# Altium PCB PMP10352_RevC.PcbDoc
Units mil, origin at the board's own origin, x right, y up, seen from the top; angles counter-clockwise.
Board outline 1810 x 910 mil, 4 copper layers (Top Layer, MidLayer1, MidLayer2, Bottom Layer), stack 61.2 mil thick; 57 components, 29 nets, 148 pads, 42 vias.
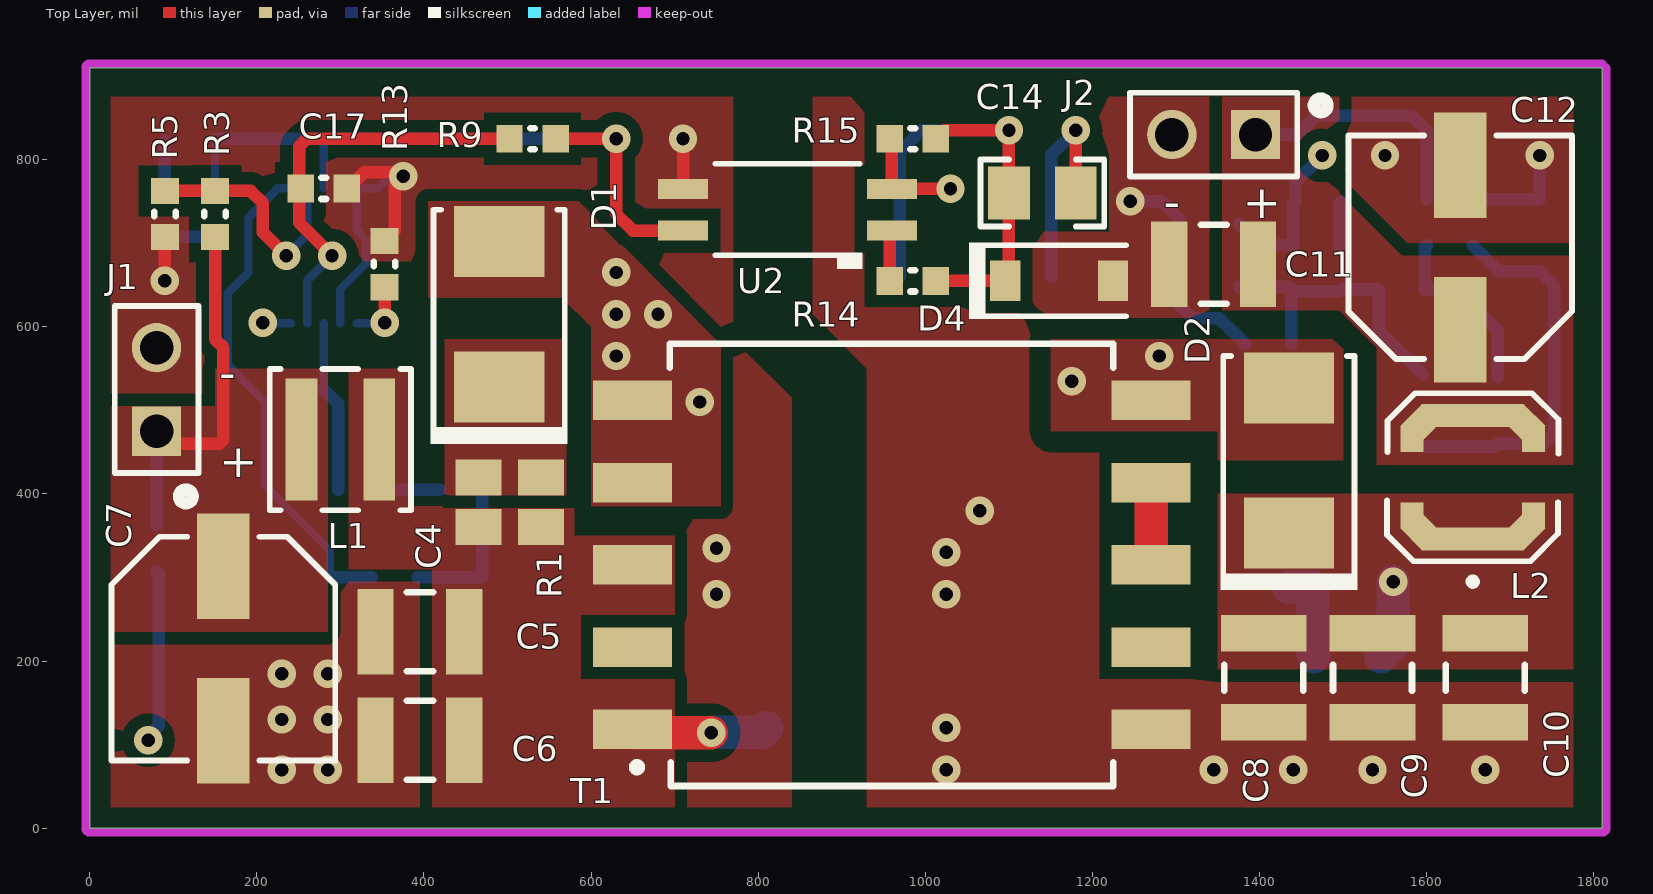
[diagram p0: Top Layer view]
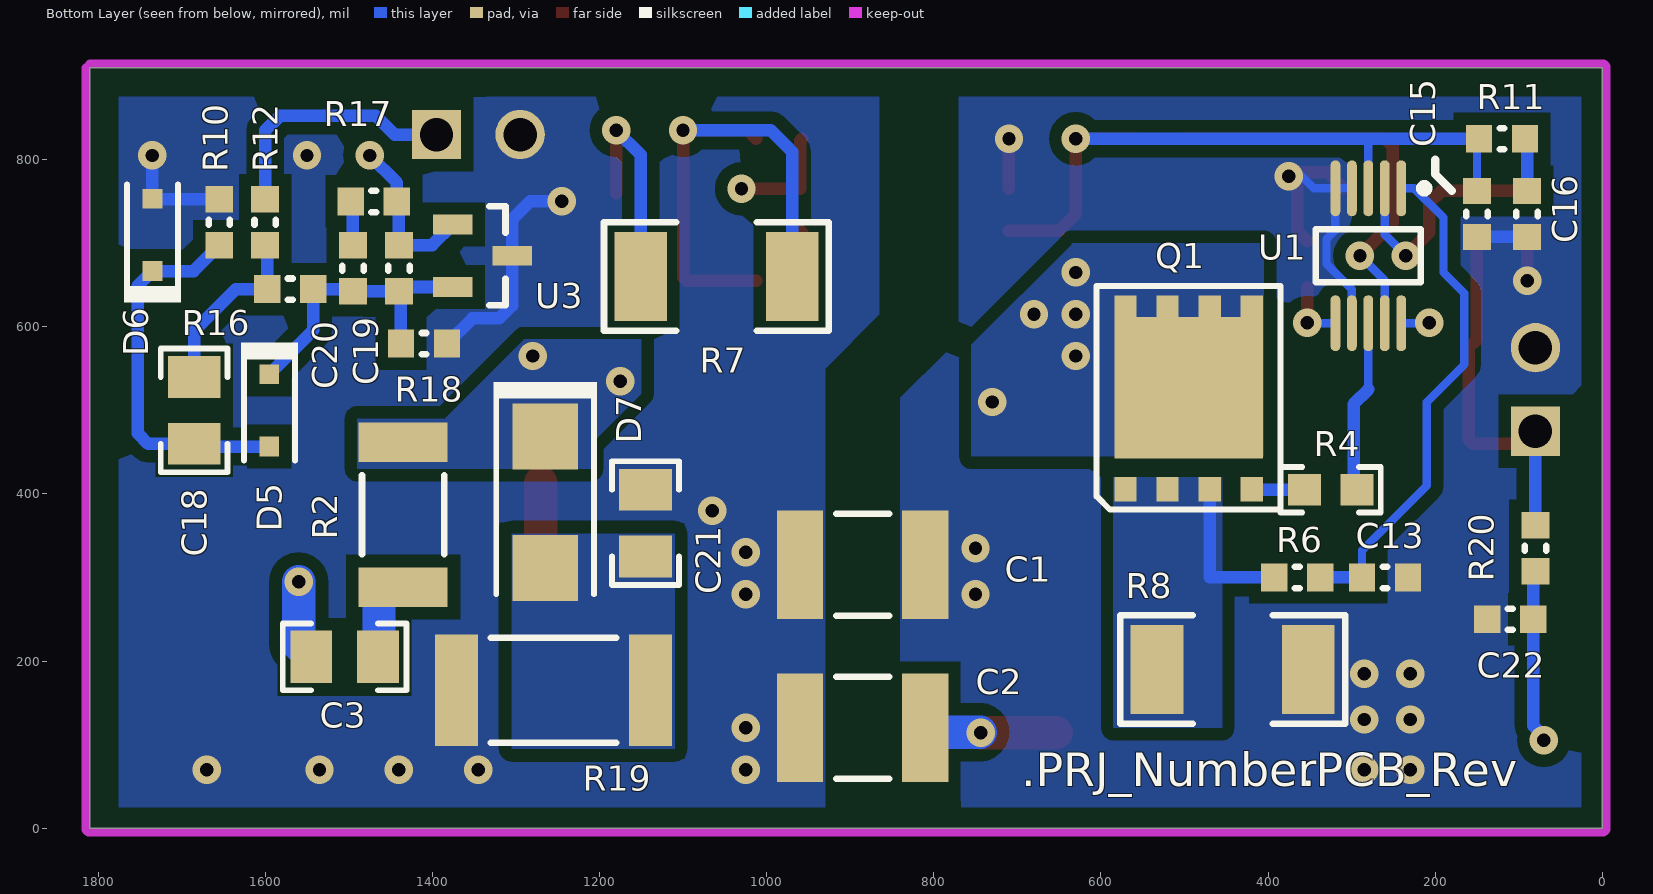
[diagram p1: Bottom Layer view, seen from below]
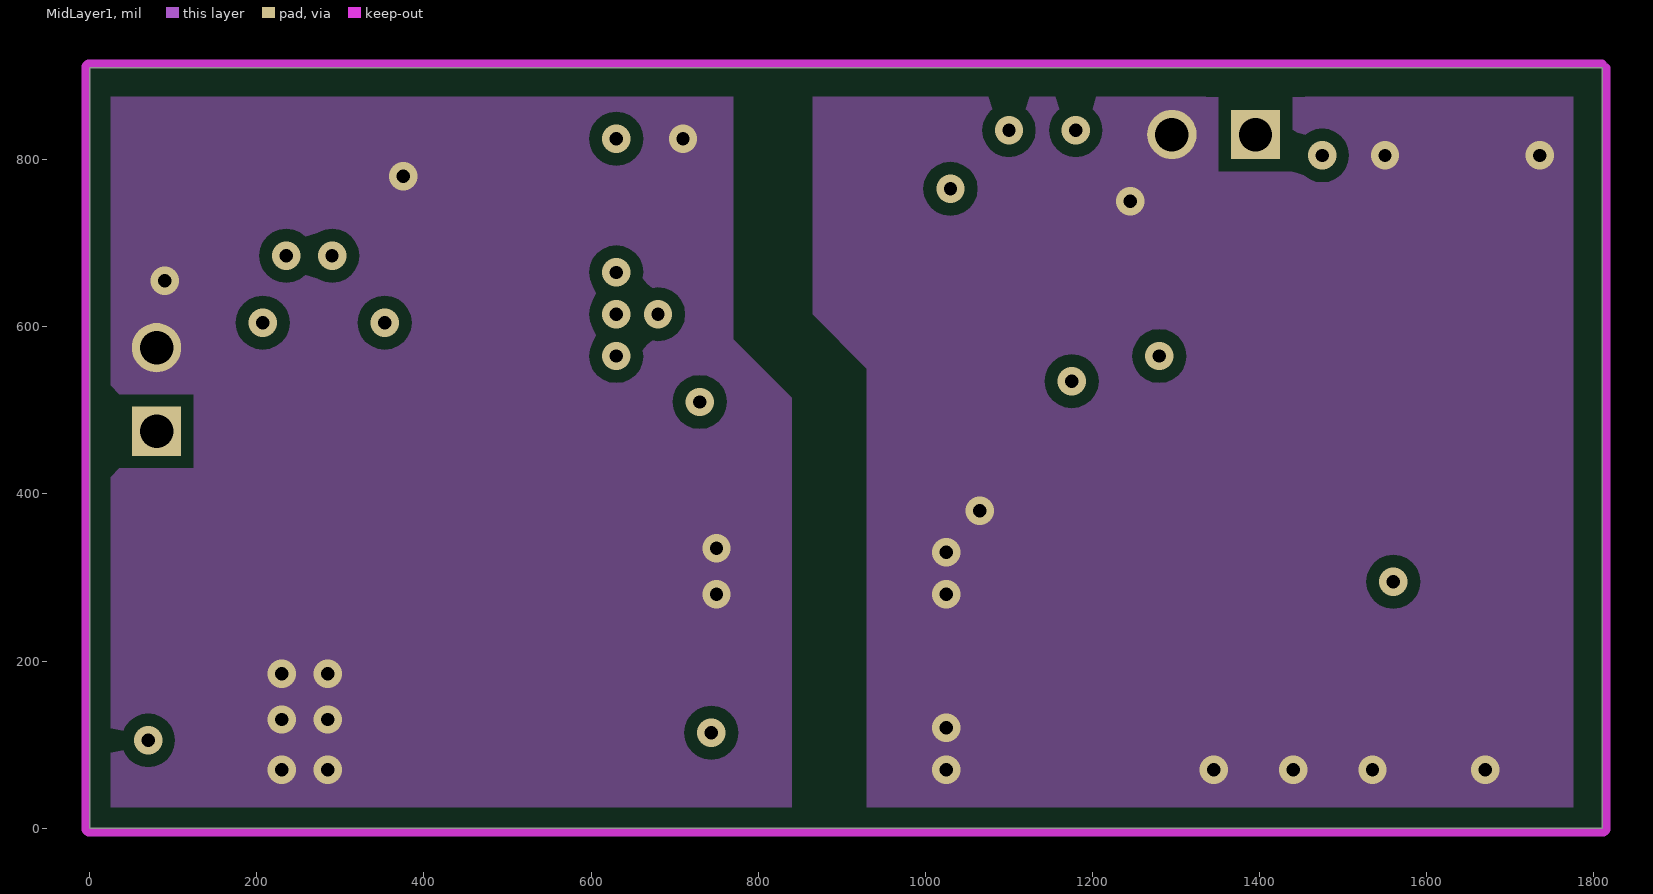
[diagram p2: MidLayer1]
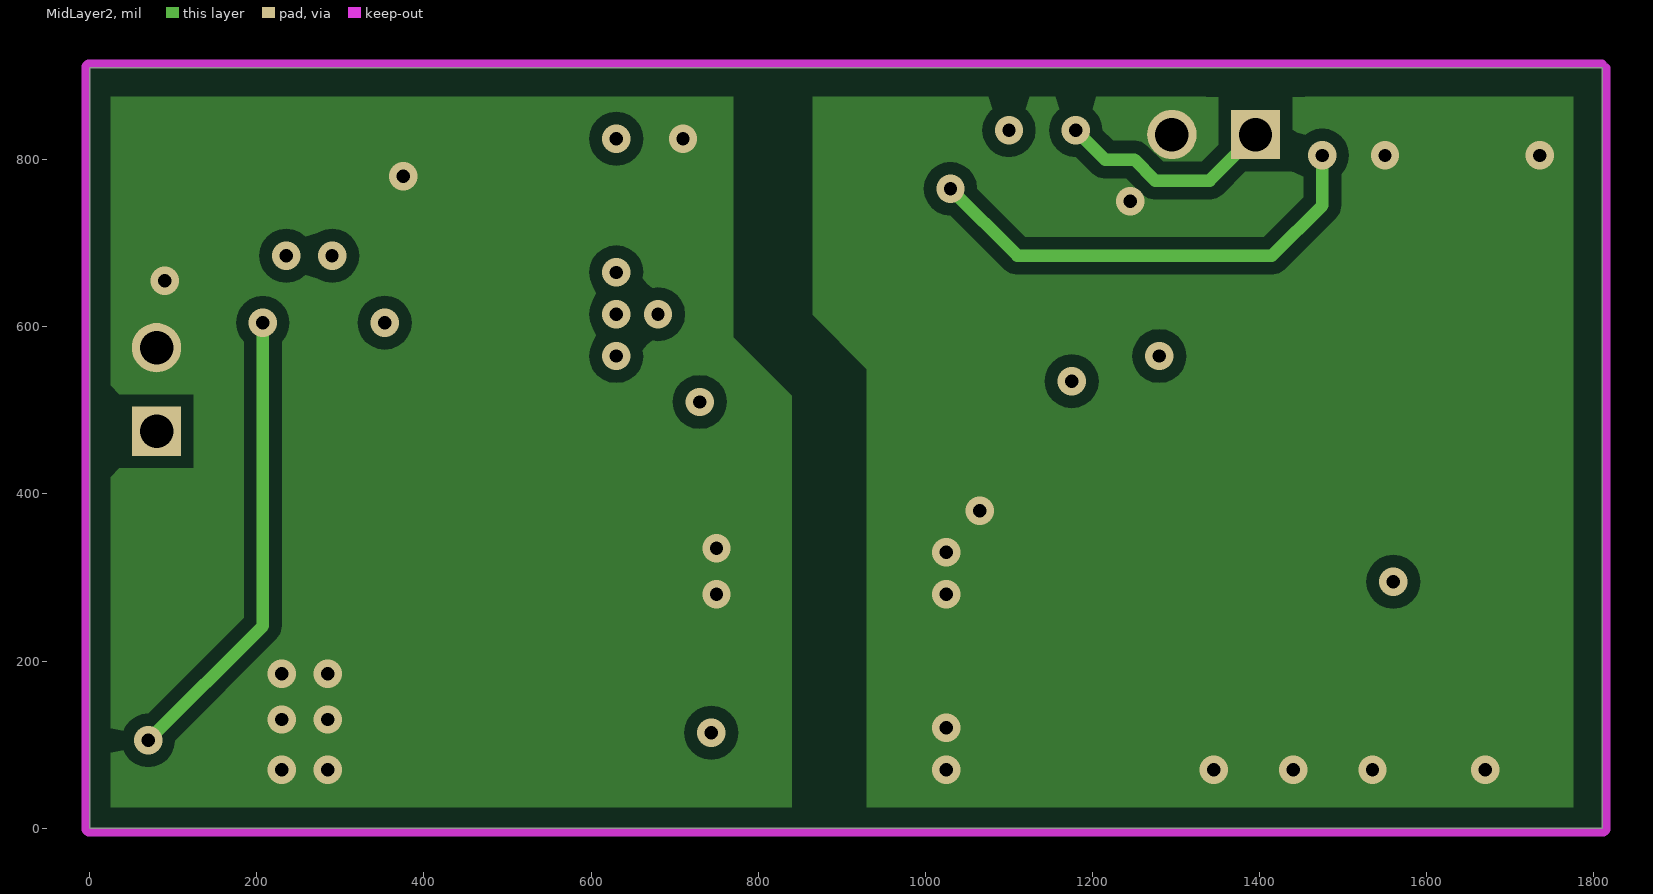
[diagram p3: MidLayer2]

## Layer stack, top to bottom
Top Solder: solder mask 0.4, Solder Resist, Dk 3.5
Top Layer: signal copper 2.8
Dielectric1: core 20, FR-4, Dk 4.8
MidLayer1: signal copper 2.8
Dielectric2: prepreg 10, FR-4, Dk 4.8
MidLayer2: signal copper 2.8
Dielectric3: core 20, FR-4, Dk 4.8
Bottom Layer: signal copper 2.8
Bottom Solder: solder mask 0.4, Solder Resist, Dk 3.5

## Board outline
0,0 1810,0 1810,910 0,910

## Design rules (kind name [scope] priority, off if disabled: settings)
AcuteAngle [All] p1: minimum=4.50000000000000E+0001 checktracksonly=FALSE
AssemblyTestPointUsage [All] p1: valid=2
Clearance Clearance_2 [InNamedPolygon('Top Layer-D2_2')] p1: gap=25 ignorepadtopadclearanceinfootprint=FALSE except(0: Arc-Hole Track-Hole SMDPad-Hole THPad-Hole Via-Hole Fill-Hole Poly-Hole Region-Hole Text-Hole)
Clearance Clearance_1 [InNamedPolygon('Bottom Layer-D2_2')] p2: gap=25 ignorepadtopadclearanceinfootprint=FALSE except(0: Arc-Hole Track-Hole SMDPad-Hole THPad-Hole Via-Hole Fill-Hole Poly-Hole Region-Hole Text-Hole)
Clearance Clearance_BoardEdge_MountingHoles [OnCopper and InComponentClass('Mounting Holes') vs IsKeepOut] p3: gap=40 ignorepadtopadclearanceinfootprint=FALSE except(0: Arc-Hole Track-Hole SMDPad-Hole THPad-Hole Via-Hole Fill-Hole Poly-Hole Region-Hole Text-Hole)
Clearance Clearance_BoardEdge_Poly [OnCopper and InPoly vs IsKeepOut] p4: gap=25 ignorepadtopadclearanceinfootprint=FALSE except(0: Arc-Hole Track-Hole SMDPad-Hole THPad-Hole Via-Hole Fill-Hole Poly-Hole Region-Hole Text-Hole)
Clearance Clearance_BoardEdge [OnCopper and Not InComponentClass('Logo') and not InComponentClass('FiducialMark') and not InRegion(1000,500,4000,800) and Not IsKeepout vs IsKeepOut] p5: gap=50 ignorepadtopadclearanceinfootprint=FALSE except(0: Arc-Hole Track-Hole SMDPad-Hole THPad-Hole Via-Hole Fill-Hole Poly-Hole Region-Hole Text-Hole)
Clearance Clearance_Poly [InPolygon] p6: gap=15 ignorepadtopadclearanceinfootprint=FALSE except(0: Arc-Hole Track-Hole SMDPad-Hole THPad-Hole Via-Hole Fill-Hole Poly-Hole Region-Hole Text-Hole)
Clearance [All] p7: gap=7 ignorepadtopadclearanceinfootprint=FALSE except(0: Arc-Hole Track-Hole SMDPad-Hole THPad-Hole Via-Hole Fill-Hole Poly-Hole Region-Hole Text-Hole)
ComponentClearance ComponentClearance_Shunt [InComponentClass('Header') vs InComponentClass('Shunt')] p1: gap=0 collisioncheckmode=3 verticalgap=0 showdistances=FALSE
ComponentClearance ComponentClearance_MountingHoles_FiducialMarks [InComponentClass('Mounting Holes') vs InComponentClass('FiducialMark')] p2: gap=50 collisioncheckmode=3 verticalgap=10 showdistances=FALSE
ComponentClearance ComponentClearance_Logo [InComponentClass('Logo')] p3: gap=50 collisioncheckmode=3 verticalgap=10 showdistances=FALSE
ComponentClearance ComponentClearance_ScrewToNut [(HasFootprint('NY PMS 440 0025 PH')) vs (HasFootprint('Keystone_1902C'))] p4: gap=5 collisioncheckmode=3 verticalgap=10 showdistances=FALSE
ComponentClearance ComponentClearance_MountingHoles [InComponentClass('Mounting Holes')] p5: gap=250 collisioncheckmode=3 verticalgap=100000 showdistances=FALSE
ComponentClearance ComponentClearance_SmallPassives [HasFootprint('0201*') or HasFootprint('0402*') or HasFootprint('0508') or HasFootprint('0603*') or HasFootprint('0612') or HasFootprint('0805*') or HasFootprint('0815*') or HasFootprint('0830*') or HasFootprint('1206*') or HasFootprint('1210*') or HasFootprint('1808*') or HasFootprint('1812*') or HasFootprint('1825*') or HasFootprint('2010*') or HasFootprint('2220*') or HasFootprint('2225*') or HasFootprint('2512*') or HasFootprint('2728*') or HasFootprint('3518*') vs HasFootprint('0201*') or HasFootprint('0402*') or HasFootprint('0508') or HasFootprint('0603*') or HasFootprint('0612') or HasFootprint('0805*') or HasFootprint('0815*') or HasFootprint('0830*') or HasFootprint('1206*') or HasFootprint('1210*') or HasFootprint('1808*') or HasFootprint('1812*') or HasFootprint('1825*') or HasFootprint('2010*') or HasFootprint('2220*') or HasFootprint('2225*') or HasFootprint('2512*') or HasFootprint('2728*') or HasFootprint('3518*')] p6: gap=15 collisioncheckmode=3 verticalgap=10 showdistances=FALSE
ComponentClearance ComponentClearance_THtoSMT [IsThruComponent vs IsSMTComponent] p7: gap=50 collisioncheckmode=3 verticalgap=30 showdistances=FALSE
ComponentClearance ComponentClearance_THtoTH [IsThruComponent vs IsThruComponent] p8: gap=50 collisioncheckmode=3 verticalgap=30 showdistances=FALSE
ComponentClearance [All] p9: gap=30 collisioncheckmode=3 verticalgap=10 showdistances=FALSE
DiffPairsRouting [All] p1: maxlimit=100 minlimit=10 mostfreqgap=10 toplayer_minwidth=15 toplayer_maxwidth=15 toplayer_prefwidth=15 midlayer1_minwidth=15 midlayer1_maxwidth=15 midlayer1_prefwidth=15 midlayer2_minwidth=15 midlayer2_maxwidth=15 midlayer2_prefwidth=15 bottomlayer_minwidth=15 bottomlayer_maxwidth=15 bottomlayer_prefwidth=15 maxuncoupledlength=1000
FabricationTestPointUsage TestPointUsage [All] p1: valid=2 allowmultiple=FALSE
FabricationTestpoint Testpoint [All] p1: side=3 testpointundercomponent=TRUE minsize=40 maxsize=100 preferedsize=60 minholesize=0 maxholesize=40 preferedholesize=32 testpointgrid=1 allowsidetop=TRUE allowsidebottom=TRUE usegrid=TRUE gridtolerance=0.01
FanoutControl Fanout_LCC [IsLCC] p1: bgadir=Out bgaviamode=Centered fanoutstyle=Auto fanoutdirection=Alternating viagrid=1 // Fanout_LCC (Default Rule)
FanoutControl Fanout_BGA [IsBGA] p2: bgadir=Out bgaviamode=Centered fanoutstyle=Auto fanoutdirection=Alternating viagrid=1 // Fanout_BGA (Default Rule)
FanoutControl Fanout_Default [All] p4: bgadir=Out bgaviamode=Centered fanoutstyle=Auto fanoutdirection=Alternating viagrid=1 // Fanout_Default (Default Rule)
FanoutControl Fanout_Small [(CompPinCount < 5)] p5: bgadir=Out bgaviamode=Centered fanoutstyle=Auto fanoutdirection=OutThenIn viagrid=1 // Fanout_Small (Default Rule)
HoleSize [All] p1: absolutevalues=TRUE maxlimit=251 minlimit=8 maxpercent=80.000 minpercent=20.000
MinimumAnnularRing MinimumAnnularRing_ThermalPadVias [IsVia and InAnyComponent] p1: minimumring=5.91
MinimumAnnularRing [All] p2: minimumring=9
MinimumSolderMaskSliver MinimumSolderMaskSliver_Logo [InComponentClass('Logo') vs InComponentClass('Logo')] p1: minsoldermaskwidth=0.7
MinimumSolderMaskSliver [All] p2: minsoldermaskwidth=3.94
PlaneConnect [All] p1: planeconnectstyle=Relief reliefexpansion=10 reliefentries=4 reliefconductorwidth=10 reliefairgap=10
PolygonConnect [All] p1: connectstyle=Direct reliefconductorwidth=10 reliefentries=4 polygonreliefangle="90 Angle" airgapwidth=10
RoutingVias ThermalPadVias [IsVia and InAnyComponent] p1: holewidth=7.87 width=19.68 viastyle="Through Hole" minholewidth=7.87 minwidth=19.68 maxholewidth=12.99 maxwidth=23.62
RoutingVias [All] p2: holewidth=16 width=34 viastyle="Through Hole" minholewidth=7.87 minwidth=26 maxholewidth=40 maxwidth=65
SMDToCorner [All] p1: distance=30000
SilkToSilkClearance [All] p1: silktosilkclearance=5
SilkToSolderMaskClearance SilkscreenOverComponentPads [IsPad] p1: minsilkscreentomaskgap=5 clearancetoexposedcopper=TRUE
SolderMaskExpansion [All] p1: expansion=1.97
Width [All] p1: maxlimit=100 minlimit=6 preferedwidth=10 checkconnectedcopper=TRUE
16 further rules are at their usual default settings.

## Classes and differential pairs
component class Header: J1 J2

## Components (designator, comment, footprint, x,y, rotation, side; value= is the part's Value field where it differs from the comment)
C1 "C4532X7R3D222K" 1812L 885,315 r180 bottom value=2200pF
C2 "C4532X7R3D222K" 1812L 885,120 r180 bottom value=2200pF
C3 "GRM21A5C2E101JW01D" 0805_HV 1505,205 r180 bottom value=100pF
C4 "C2012X7R1H224K" 0805L 465,390 r90 top value=0.22uF
C5 "C3225X7R1E106K" 1210L 395,235 r180 top value=10uF
C6 "C3225X7R1E106K" 1210L 395,105 r180 top value=10uF
C7 "EEE-FK1E101XP" SM_RADIAL_D8 160,215 r270 top value=100uF
C8 "GRM32ER72A225KA35L" 1210L 1405,180 r270 top value=2.2uF
C9 "GRM32ER72A225KA35L" 1210L 1535,180 r270 top value=2.2uF
C10 "GRM32ER72A225KA35L" 1210L 1670,180 r270 top value=2.2uF
C11 "GRM32ER72A225KA35L" 1210L 1345,675 r180 top value=2.2uF
C12 "EEE-FK1J220XP" SM_RADIAL_D8 1640,695 r90 top value=22uF
C13 "C1608C0G1H101J" 0603L 260,300 r180 bottom value=100pF
C14 "C2012X7R2A104K125AA" 0805_HV 1140,760 r180 top value=0.1uF
C15 "C1608C0G1H101J" 0603L 150,735 r270 bottom value=100pF
C16 "C1608X7R1E224K080AC" 0603L 90,735 r270 bottom value=0.22uF
C17 "C1608X7R1C105K080AC" 0603L 280,765.71 r0 top value=1uF
C18 "C2012X7R2A473K125AA" 0805_HV 1685,500 r270 bottom value=0.047uF
C19 "C1608C0G1H101J" 0603L 1440,670 r90 bottom value=100pF
C20 "C1608X7R1E104K080AA" 0603L 1495,670 r90 bottom value=0.1uF
C21 "GRM21BR72E103KW03L" 0805_HV 1145,365 r90 bottom value=0.01uF
C22 "C1608X7R1E224K080AC" 0603L 110,250 r0 bottom value=0.22uF
D1 "ES3AB-13-F" SMB 490,615 r90 top value=50V
D2 "ES2D-13-F" SMB 1435,440 r90 top value=200V
D4 "MMSZ5239B-7-F" SOD-123 1160,655 r0 top value=9.1V
D5 "MMDL914-TP" sod-323 1595,500 r270 bottom value=100V
D6 "MMDL914-TP" sod-323 1735,710 r90 bottom value=100V
D7 "ES1D-13-F" SMA 1265,390 r270 bottom value=200V
J1 "PEC02SAAN" CONN_PEC02SAAN 80,525 r90 top
J2 "PEC02SAAN" CONN_PEC02SAAN 1345,830 r180 top
L1 "XAL4020-102MEB" XAL4020 300,465 r0 top value=1uH
L2 "LPS4012-102NLB" LPS4012 1655,420 r90 top value=1uH
Q1 "CSD18504Q5A" TRANS_NexFET_Q5A 495,515 r90 bottom value=40V
R1 "CRCW080524K0JNEA" 0805L 540,390 r270 top value=24k
R2 "CRCW2010200RJNEF" 2010L 1435,375 r270 bottom value=200
R3 "CRCW0603100KFKEA" 0603L 150,735 r270 top value=100k
R4 "CRCW060310R0JNEA" 0603 325,405 r0 bottom value=10
R5 "CRCW060323K7FKEA" 0603L 90,735 r90 top value=23.7k
R6 "CRCW06031K00FKEA" 0603L 365,300 r180 bottom value=1.00k
R7 "CRCW20105K60JNEF" 2010 1060,660 r0 bottom value=5.6k
R8 "CSRN2010FK15L0" 2010 442.24,190 r0 bottom value=0.015
R9 "CRCW06033K32FKEA" 0603L 530,825 r0 top value=3.32k
R10 "CRCW0603100KFKEA" 0603L 1655,725 r270 bottom value=100k
R11 "CRCW0603750RFKEA" 0603L 120,825 r0 bottom value=750
R12 "ERJ-3GEY0R00V" 0603L 1600,725 r90 bottom value=0
R13 "CRCW060382K5FKEA" 0603L 352.83,675 r270 top value=82.5k
R14 "CRCW06031K00FKEA" 0603L 985,655 r0 top value=1.00k
R15 "CRCW06034K99FKEA" 0603L 985,825 r0 top value=4.99k
R16 "CRCW060349K9FKEA" 0603L 1570,645 r0 bottom value=49.9k
R17 "CRCW060310K0FKEA" 0603L 1470,750 r180 bottom value=10.0k
R18 "CRCW06032K74FKEA" 0603L 1410,579.76 r0 bottom value=2.74k
R19 "CRCW251227K0JNEG" 2512 1255,165 r180 bottom value=27k
R20 "CRCW060310R0JNEA" 0603L 80,335 r90 bottom value=10
T1 "PA4191NL" PULSE_PA4191NL 960,315 r90 top value="10 uH"
U1 "LM3481MM" MUB10A_N 280,685 r270 bottom
U2 "HMHA2801A" MFP04A 835,740 r180 top
U3 "TL431AIDBZ" DBZ0003A_L 1340,685 r180 bottom

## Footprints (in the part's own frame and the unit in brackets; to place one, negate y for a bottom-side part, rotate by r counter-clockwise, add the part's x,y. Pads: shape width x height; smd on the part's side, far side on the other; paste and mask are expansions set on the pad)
0603 [mm] "0603 from SM-752 data"
  rect 1x0.95 smd: 1(-0.8,0) 2(0.8,0)
  silkscreen extent -1.52,-0.69 1.52,0.69, body extent -0.87,-0.47 0.87,0.47, height 1
0603L [mm] "0603 from SM-752 data"
  rect 0.8x0.85 smd: 1(-0.7,0) 2(0.7,0)
  silkscreen extent -0.07,-0.33 0.07,0.33, body extent -0.87,-0.47 0.87,0.47, height 0.85
0805_HV [mil] "0805 with 30mil clearance between pads"
  rect 50x63 smd: 1(-40,0) 2(40,0)
  silkscreen extent -74,-40 74,40, body extent -43,-29 43,29, height 57
0805L [mm] "0805 from SM-752 data"
  rect 1.1x1.4 smd: 1(-0.75,0) 2(0.75,0)
  body extent -1.1,-0.72 1.1,0.72, height 1.1
1210L [mm] "1210 from SM-752 data"
  rect 1.1x2.6 smd: 1(-1.35,0) 2(1.35,0)
  silkscreen extent -0.4,-1.2 0.4,1.2, body extent -1.7,-1.35 1.7,1.35, height 1.35
1812L [mm]
  rect 1.4x3.3 smd: 1(-1.9,0) 2(1.9,0)
  silkscreen extent -0.8,-1.55 0.8,1.55, body extent -2.4,-1.7 2.4,1.7, height 1.35
2010 [mm] "Chip Capacitor, Body 5.08x2.54mm, IPC Medium Density"
  rect 1.6x2.7 smd: 1(-2.3,0) 2(2.3,0)
  silkscreen extent -3.42,-1.65 3.42,1.65, body extent -2.73,-1.45 2.73,1.45, height 1.66
2010L [mm]
  rect 1.2x2.7 smd: 1(-2.2,0) 2(2.2,0)
  silkscreen extent -1.2,-1.25 1.2,1.25, body extent -2.73,-1.45 2.73,1.45, height 1.66
2512 [mm] "Chip Resistor, Body 6.3x3.2mm, IPC Medium Density"
  rect 1.3x3.4 smd: 1(-2.95,0) 2(2.95,0)
  silkscreen extent -1.9,-1.6 1.9,1.6, body extent -3.22,-1.67 3.22,1.67, height 0.71
CONN_PEC02SAAN [mm] "SULLINS"
  rect 1.5x1.5 hole 1.016: 1(-1.27,0)
  round 1.5 hole 1.016: 2(1.27,0)
  silkscreen extent -3.45,-1.27 2.54,1.27, body extent -2.54,-1.27 2.54,1.27, height 8.38
DBZ0003A_L [mm] "SOT23, 3-Leads, Body 2.9x1.3mm, Pitch 0.95mm, Lead Span 2.4mm, IPC High Density"
  rect 1.2x0.6 smd: 1(-0.9,0.95) 2(-0.9,-0.95) 3(0.9,0)
  silkscreen extent 0.2,-1.5 0.7,1.5, body extent -1.26,-1.46 1.26,1.46, height 0.96
LPS4012 [mm] "Coilcraft recommended land pattern.  Document 433-2, rev 10/20/08"
  rect 0.7x3.124 smd: 1(-1.881,0) 2(1.881,0)
  rect 0.902x0.801 smd rot 45: 1(-1.592,1.605) 2(1.592,-1.605)
  rect 0.902x0.801 smd rot 135: 1(-1.592,-1.605) 2(1.592,1.605)
  rect 0.812x0.7 smd: 1(-1.168,1.85) 1(-1.168,-1.85) 2(1.168,1.85) 2(1.168,-1.85)
  silkscreen extent -3.26,-2.6 2.55,2.6, body extent -2.05,-2.05 2.05,2.05, height 1.22
MFP04A [mm] "FAIRCHILD optocoupler"
  rect 1.52x0.61 smd: 1(-3.175,0.635) 2(-3.175,-0.635) 3(3.175,-0.635) 4(3.175,0.635)
  silkscreen extent -2.28,-1.4 2.2,1.8, body extent -3.6,-1.34 3.6,1.34, height 2.39
MUB10A_N [mm] "TSSOP, 10-Leads, Body 3x3mm, Pitch 0.5mm, IPC Medium Density"
  oval 1.7x0.3 smd: 1(-2.05,1) 2(-2.05,0.5) 3(-2.05,0) 4(-2.05,-0.5) 5(-2.05,-1) 6(2.05,-1) 7(2.05,-0.5) 8(2.05,0) 9(2.05,0.5) 10(2.05,1)
  silkscreen extent -2.17,-1.6 0.8,1.82, body extent -1.6,-1.6 1.6,1.6, height 1.09
PULSE_PA4191NL [mm] "SMD, 10-Leads, Body 13.44 x 13.44 mm, Pitch 2.5 mm"
  rect 1.2x2.4 smd: 1(-5,7.88) 2(-2.5,7.88) 3(0,7.88) 4(2.5,7.88) 5(5,7.88) 6(5,-7.88) 7(2.5,-7.88) 8(0,-7.88) 9(-2.5,-7.88) 10(-5,-7.88)
  silkscreen extent -6.72,-6.72 6.72,7.87, body extent -6.72,-6.72 6.72,6.72, height 12.45
SM_RADIAL_D8 [mm] "6.3 x 7.7mm:  Panasonic D8"
  rect 3.2x1.6 smd: 1(-2.5,0) 2(2.5,0)
  silkscreen extent -3.4,-3.4 3.4,3.4, body extent -3.4,-3.4 3.4,3.4, height 8.01
SMA [mm] "Molded Diode, 2-Leads, Body 4.3x2.6mm, IPC Medium Density, based on OnSemi component dimensions and land pattern"
  rect 2x2 smd: 1(-2,0) 2(2,0)
  silkscreen extent -3.66,-1.57 2.79,1.57, body extent -2.6,-1.3 2.6,1.3, height 2.42
SMB [mil] "Molded Diode, 2-Leads, Body 5.4x3.6mm, IPC Medium Density, based on OnSemi component dimensions"
  rect 85x107.99 smd: 1(-87.01,0) 2(87.01,0)
  silkscreen extent -155,-82 125,82, body extent -106,-71 106,71, height 91
SOD-123 [mm] "On Semi recommended land pattern"
  rect 0.915x1.22 smd: 1(-1.637,0) 2(1.637,0)
  silkscreen extent -2.74,-1.17 2.03,1.17, body extent -1.93,-0.9 1.93,0.9, height 1.35
sod-323 [mm] "NXP recommended land pattern"
  rect 0.6x0.6 smd paste-0.05: 1(-1.1,0) 2(1.1,0)
  silkscreen extent -2.06,-0.86 1.53,0.86, body extent -1.3,-0.67 1.3,0.68, height 1.1
TRANS_NexFET_Q5A [mm] "TI recommended land pattern (nominal) M0139-01"
  rect 0.75x0.675 smd paste-0.1 mask+0.051: 1(-2.776,1.917) 2(-2.776,0.639) 3(-2.776,-0.639) 4(-2.776,-1.917)
  rect 0.655x0.675 smd paste-0.1 mask+0.051: 5(2.776,-1.917) 6(2.776,-0.639) 7(2.776,0.639) 8(2.776,1.917)
  rect 4.295x4.51 smd paste-2.2 mask+0.051: 9(0.301,0)
  silkscreen extent -3.4,-2.8 3.4,2.8, body extent -3.05,-2.5 3.05,2.5, height 1.11
XAL4020 [mil] "Coilcraft XAL4020 7/18/12"
  rect 38x146 smd: 1(-46.5,0) 2(46.5,0)
  silkscreen extent -84,-84 84,84, body extent -84,-84 84,84, height 83

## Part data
C1 C2: "CAP, CERM, 2200pF, 2000V, +/-10%, X7R, 1812", Cap_Case=1812, Manufacturer=TDK, Supplier Part Number 1=445-2389-1-ND, TempCo=X7R, Tolerance_%=10, Value1=Unknown, Value2=2000V, ValueDisplayed=2200pF
C3: "CAP, CERM, 100 pF, 250 V, +/- 5%, C0G/NP0, 0805", Cap_Case=0805, Manufacturer=MuRata, Supplier Part Number 1=490-5542-1-ND, TempCo=C0G/NP0, Tolerance_%=5, Value1=Unknown, Value2=250V, ValueDisplayed=100pF
C4: "CAP, CERM, 0.22uF, 50V, +/-10%, X7R, 0805", Cap_Case=0805, Manufacturer=TDK, Supplier Part Number 1=445-1350-1-ND, TempCo=X7R, Tolerance_%=10, Value1="0.0117 ohm", Value2=50V, ValueDisplayed=0.22µF
C5 C6: library part C3225X7R1E106M, "CAP, CERM, 10uF, 25V, +/-20%, X7R, 1210", Cap_Case=1210, Manufacturer=TDK, Supplier Part Number 1=445-1434-1-ND, TempCo=X7R, Tolerance_%=20, Value1="0.0027 ohm", Value2=25V, ValueDisplayed=10µF
C7: "CAP, AL, 100uF, 25V, +/-20%, 0.34 ohm, SMD", Cap_Case=D8, Manufacturer=Panasonic, Supplier Part Number 1=PCE3797CT-ND, Tolerance_%=20, Value1="0.34 ohm", Value2=25V, ValueDisplayed=100µF
C8 C9 C10 C11: "CAP, CERM, 2.2uF, 100V, +/-10%, X7R, 1210", Cap_Case=1210, Manufacturer=MuRata, Supplier Part Number 1=490-3385-1-ND, TempCo=X7R, Tolerance_%=10, Value1="0.007 ohm", Value2=100V, ValueDisplayed=2.2µF
C12: "CAP, AL, 22uF, 63V, +/-20%, 1.2 ohm, SMD", Cap_Case=D8, Manufacturer=Panasonic, Supplier Part Number 1=PCE3821CT-ND, Tolerance_%=20, Value1="1.2 ohm", Value2=63V, ValueDisplayed="22 µF"
C13 C15 C19: "CAP, CERM, 100pF, 50V, +/-5%, C0G/NP0, 0603", Cap_Case=0603, Manufacturer=TDK, Supplier Part Number 1=445-1281-1-ND, TempCo=C0G/NP0, Tolerance_%=5, Value1="0.1679 ohm", Value2=50V, ValueDisplayed=100pF
C14: "CAP, CERM, 0.1 µF, 100 V,+/- 10%, X7R, 0805", Cap_Case=0805, Manufacturer=TDK, Supplier Part Number 1=445-1418-1-ND, TempCo=X7R, Tolerance_%=10, Value1="0.020726 ohm", Value2=100V, ValueDisplayed=0.1µF
C16 C22: "CAP, CERM, 0.22 µF, 25 V,+/- 10%, X7R, 0603", Cap_Case=0603, Manufacturer=TDK, Supplier Part Number 1=445-5191-1-ND, TempCo=X7R, Tolerance_%=10, Value2=25V, ValueDisplayed=0.22µF
C17: "CAP, CERM, 1 µF, 16 V,+/- 10%, X7R, 0603", Cap_Case=0603, Manufacturer=TDK, Supplier Part Number 1=445-1604-1-ND, TempCo=X7R, Tolerance_%=10, Value1="0.0057 ohm", Value2=16V, ValueDisplayed=1µF
C18: "CAP, CERM, 0.047 µF, 100 V,+/- 10%, X7R, 0805", Cap_Case=0805, Manufacturer=TDK, Supplier Part Number 1=445-2276-1-ND, TempCo=X7R, Tolerance_%=10, Value1="0.049089 ohm", Value2=100V, ValueDisplayed=0.047µF
C20: "CAP, CERM, 0.1 µF, 25 V,+/- 10%, X7R, 0603", Cap_Case=0603, Manufacturer=TDK, Supplier Part Number 1=445-1316-1-ND, TempCo=X7R, Tolerance_%=10, Value2=25V, ValueDisplayed=0.1µF
C21: "CAP, CERM, 0.01 µF, 250 V,+/- 10%, X7R, 0805", Cap_Case=0805, Manufacturer=MuRata, Supplier Part Number 1=490-3534-1-ND, TempCo=X7R, Tolerance_%=10, Value2=250V, ValueDisplayed=0.01µF
D1: "Diode, Superfast Rectifier, 50V, 3A, SMB", Manufacturer="Diodes Inc.", Supplier Part Number 1=ES3AB-FDICT-ND, Value1=3A, Value2=0.9V
D2: "Diode, Ultrafast, 200V, 2A, SMB", Manufacturer="Diodes Inc.", Supplier Part Number 1=ES2D-FDICT-ND, Value1=2A, Value2=0.92V
D4: "Diode, Zener, 9.1V, 500mW, SOD-123", Manufacturer="Diodes Inc.", Power_W=0.5, Supplier Part Number 1=MMSZ5239B-FDICT-ND, Value1=0.5W
D5 D6: "Diode, Switching, 100V, 0.2A, SOD-323", Manufacturer="Micro Commercial Components", Supplier Part Number 1=MMDL914-TPMSCT-ND, Value1=0.2A, Value2=1V
D7: "Diode, Ultrafast, 200V, 1A, SMA", Manufacturer="Diodes Inc.", Supplier Part Number 1=ES1D-FDICT-ND, Value1=1A, Value2=0.92V
J1 J2: "Header, 100mil, 2x1, Tin, TH", Manufacturer="Sullins Connector Solutions", Supplier Part Number 1=S1012E-02-ND
L1: "Inductor, Shielded, Composite, 1uH, 8.75A, 0.01 ohm, SMD", Manufacturer=Coilcraft, Supplier Part Number 1=994-XAL4020-102MEB, Value1="0.01 ohm", Value2=8.75A, ValueDisplayed=1µH
L2: "Inductor, Shielded Drum Core, Ferrite, 1uH, 2.4A, 0.06 ohm, SMD", Manufacturer=Coilcraft, Value1="0.06 ohm", Value2=2.4A, ValueDisplayed=1µH
Q1: "MOSFET, N-CH, 40V, 15A, SON 5x6mm", Alternate Manufacturer=None, Manufacturer="Texas Instruments", Supplier Part Number 1=296-30572-1-ND, Value1="0.0098 ohm", Value2="7.7 nC"
R1: "RES, 24k ohm, 5%, 0.125W, 0805", Manufacturer=Vishay-Dale, Power_W=0.125, Supplier Part Number 1=71-CRCW080524K0JNEA, TempCo="200 ppm/C", Tolerance_%=5, Value1=5%, Value2=0.125W, Value_Code=24k0
R2: "RES, 200 ohm, 5%, 0.75W, 2010", Manufacturer=Vishay-Dale, Power_W=0.75, Supplier Part Number 1=541-200WCT-ND, TempCo="200 ppm/C", Tolerance_%=5, Value1=5%, Value2=0.75W, Value_Code=200R
R3: "RES, 100k ohm, 1%, 0.1W, 0603", Manufacturer=Vishay-Dale, Power_W=0.1, Supplier Part Number 1=541-100KHCT-ND, TempCo="100 ppm/C", Tolerance_%=1, Value1=1%, Value2=0.1W, Value_Code=100k
R4 R20: "RES, 10, 5%, 0.1 W, 0603", Manufacturer=Vishay-Dale, Power_W=0.1, Supplier Part Number 1=541-10GCT-ND, TempCo="200 ppm/C", Tolerance_%=5, Value1=5%, Value2=0.1W, Value_Code=10R0, ValueDisplayed=10
R5: "RES, 23.7k ohm, 1%, 0.1W, 0603", Manufacturer=Vishay-Dale, Power_W=0.1, Supplier Part Number 1=541-23.7KHCT-ND, TempCo="100 ppm/C", Tolerance_%=1, Value1=1%, Value2=0.1W, Value_Code=23k7
R6 R14: "RES, 1.00k ohm, 1%, 0.1W, 0603", Manufacturer=Vishay-Dale, Power_W=0.1, Supplier Part Number 1=541-1.00KHCT-ND, TempCo="100 ppm/C", Tolerance_%=1, Value1=1%, Value2=0.1W, Value_Code=1k00
R7: "RES, 5.6 k, 5%, 0.75 W, AEC-Q200 Grade 0, 2010", Manufacturer=Vishay-Dale, Power_W=0.75, Supplier Part Number 1=541-5.6KWCT-ND, TempCo="200 ppm/C", Tolerance_%=5, Value1=5%, Value2=0.75W, Value_Code=5k60, ValueDisplayed=5.6k
R8: "RES, 0.015, 1%, 1 W, 2010", Manufacturer="Stackpole Electronics Inc", Power_W=1, Supplier Part Number 1=CSRN2010FK15L0CT-ND, TempCo="250 ppm/C", Value1=1%, Value2=1W, Value_Code=R015, ValueDisplayed=0.015
R9: "RES, 3.32k ohm, 1%, 0.1W, 0603", Manufacturer=Vishay-Dale, Power_W=0.1, Supplier Part Number 1=541-3.32KHCT-ND, TempCo="100 ppm/C", Tolerance_%=1, Value1=1%, Value2=0.1W, Value_Code=3k32
R10: "RES, 100 k, 1%, 0.1 W, 0603", Manufacturer=Vishay-Dale, Power_W=0.1, Supplier Part Number 1=541-100KHCT-ND, TempCo="100 ppm/C", Tolerance_%=1, Value1=1%, Value2=0.1W, Value_Code=100k
R11: "RES, 750, 1%, 0.1 W, 0603", Manufacturer=Vishay-Dale, Power_W=0.1, Supplier Part Number 1=541-750HCT-ND, TempCo="100 ppm/C", Tolerance_%=1, Value1=1%, Value2=0.1W, Value_Code=750R, ValueDisplayed=750
R12: "RES, 0 ohm, 5%, 0.1W, 0603", Manufacturer=Panasonic, Power_W=0.1, Supplier Part Number 1=P0.0GCT-ND, TempCo="600 ppm/C", Tolerance_%=5, Value1=5%, Value2=0.1W, Value_Code=0000
R13: "RES, 82.5k ohm, 1%, 0.1W, 0603", Manufacturer=Vishay-Dale, Power_W=0.1, Supplier Part Number 1=541-82.5KHCT-ND, TempCo="100 ppm/C", Tolerance_%=1, Value1=1%, Value2=0.1W, Value_Code=82k5
R15: "RES, 4.99k ohm, 1%, 0.1W, 0603", Manufacturer=Vishay-Dale, Power_W=0.1, Supplier Part Number 1=541-4.99KHCT-ND, TempCo="100 ppm/C", Tolerance_%=1, Value1=1%, Value2=0.1W, Value_Code=4k99
R16: "RES, 49.9k ohm, 1%, 0.1W, 0603", Manufacturer=Vishay-Dale, Power_W=0.1, Supplier Part Number 1=541-49.9KHCT-ND, TempCo="100 ppm/C", Tolerance_%=1, Value1=1%, Value2=0.1W, Value_Code=49k9
R17: "RES, 10.0k ohm, 1%, 0.1W, 0603", Manufacturer=Vishay-Dale, Power_W=0.1, Supplier Part Number 1=541-10.0KHCT-ND, TempCo="100 ppm/C", Tolerance_%=1, Value1=1%, Value2=0.1W, Value_Code=10k0
R18: "RES, 2.74k ohm, 1%, 0.1W, 0603", Manufacturer=Vishay-Dale, Power_W=0.1, Supplier Part Number 1=541-2.74KHCT-ND, TempCo="100 ppm/C", Tolerance_%=1, Value1=1%, Value2=0.1W, Value_Code=2k74
R19: "RES, 27k ohm, 5%, 1W, 2512", Manufacturer=Vishay-Dale, Power_W=1, Supplier Part Number 1=541-27KXCT-ND, TempCo="200 ppm/C", Tolerance_%=5, Value1=5%, Value2=1W, Value_Code=27k0
T1: "Transformer, 10 uH, SMT", Manufacturer="Pulse Engineering"
U1: "High Efficiency Low-Side N-Channel Controller for Switching Regulators, 10-pin MSOP", Manufacturer="National Semiconductor", PackageTopMarking=ZXTT*SJPB, PowerWise=N, Supplier Part Number 1=1798320
U2: "Optocoupler, 3.75kV RMS, SMT", Manufacturer="Fairchild Semiconductor", Supplier Part Number 1=HMHA2801A-ND
U3: "PRECISION PROGRAMMABLE REFERENCE, DBZ0003A", Alternate Manufacturer=None, Manufacturer="Texas Instruments"

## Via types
v1: diameter 34, hole 16, Top Layer to Bottom Layer, 42 vias

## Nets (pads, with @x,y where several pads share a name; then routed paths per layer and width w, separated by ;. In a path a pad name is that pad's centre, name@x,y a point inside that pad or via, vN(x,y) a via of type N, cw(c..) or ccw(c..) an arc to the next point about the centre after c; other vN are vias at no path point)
GND: C1.1 C2.1 C8.2 C9.2 C10.2 C11.2 C12.2 C21.2 D4.2 D6.2 J2.2 R10.1 R18.1 R19.1 T1.10 U3.3 | length 400.3
  Bottom Layer w15: v1(1245,750) 1282.99,750 1304.57,728.43 U3.3 1304.57,625.43 1320,610 1352.2,610 R18.1 ; R10.1 1734.25,752.56 D6.2 v1(1735,805)
  other v1: 1025,70 1345,70 1440,70 1535,70 1670,70 1025,120 1025,280 1025,330 1065,380 1550,805
NetC2_2: C2.2 C4.1 C5.1 C6.1 L1.2 R1.2 T1.1 T1.3 | length 158
  Top Layer w40: T1.1@653.6,114.31 v1(743.86,114.31)
  Bottom Layer w40: v1@744.55,115 805.2,115 C2.2
NetC3_1: C3.1 C8.1 C9.1 C10.1 D2.1 L2.1 | length 96.2
  Bottom Layer w40: C3.1 1560,220 v1(1560,295)
NetC3_2: C3.2 R2.2 | length 112.7
  Bottom Layer w40: R2.2 1463.82,288.39 1463.82,206.18 C3.2
NetC4_2: C4.2 D1.1 R1.1
NetC7_1: C7.1 J1.1 L1.1 R3.2 R20.2 | length 426.1
  Top Layer w15: J1.1@80,460 155,460 160,465 160,575 150,585 R3.2
  Bottom Layer w15: R20.2 J1.1@80,460
NetC11_1: C11.1 C12.1 C14.1 J2.1 L2.2 R7.2 R12.2 | length 828.8
  Top Layer w15: C14.1 v1(1180,835)
  MidLayer2 w15: v1(1180,835) 1215,800 1250,800 1275,775 1340,775 J2.1
  Bottom Layer w15: R7.2 1150.55,805.55 v1(1180,835) ; J2.1 1445,830 1467.5,852.5 1582.5,852.5 1600,835 R12.2
NetC13_1: C13.1 R6.2 U1.1 | length 606.8
  Bottom Layer w10: U1.1 225.04,765.71 190,730.67 190,665 165,640 165,555 210,510 210,410 287.56,332.44 C13.1
  Bottom Layer w15: C13.1 R6.2
NetC14_2: C14.2 D4.1 R7.1 R14.2 R15.2 | length 647
  Top Layer w15: R14.2 D4.1 1100,659.47 C14.2 v1(1100,835) 1022.56,835 R15.2
  Bottom Layer w15: R7.1 969.45,809.45 995,835 v1(1100,835)
NetC15_1: C15.1 R9.2 R11.2 U1.3 U2.4 | length 850
  Top Layer w15: R9.2 v1(630,825) 630,735 650,715 U2.4
  Bottom Layer w10: C15.1 R11.2@150,822.56 ; U1.3 280,825
  Bottom Layer w15: R11.2@150,825 280,825 v1(630,825)
NetC16_1: C16.1 R11.1 | length 60
  Bottom Layer w15: C16.1 R11.1@90,822.56
NetC17_1: C17.1 R9.1 U1.9 | length 495.8
  Top Layer w15: v1(290,685) 250.47,724.53 250.47,765.71 250.47,815.47 260,825 R9.1
  Bottom Layer w10: U1.9 260.31,655.31 v1(290,685)
NetC18_1: C18.1 R12.1 R16.2 | length 216.6
  Bottom Layer w15: R12.1 1597.56,695 R16.2 1635,645 1685,595 C18.1
NetC18_2: C18.2 D5.2 D6.1 R10.2 | length 458.2
  Bottom Layer w15: D5.2 1681.69,456.69 C18.2 1740,460 1752.5,472.5 1752.5,649.19 D6.1 1685.75,666.69 R10.2
NetC19_1: C19.1 C20.1 D5.1 R16.1 R18.2 U3.2 | length 358.8
  Bottom Layer w15: U3.2 1434.84,647.6 C19.1@1437.56,644.88 ; R18.2 C19.1@1437.56,644.88 ; D5.1 1542.44,595.87 R16.1 1497.56,645 C20.1 C19.1 C19.1@1437.56,644.88
NetC19_2: C19.2 R15.1 R17.2 U2.2 U3.1 | length 890.6
  Top Layer w15: R15.1 960,822.44 U2.2 v1(1030,765)
  MidLayer2 w15: v1(1030,765) 1110,685 1414.65,685 1475,745.35 v1(1475,805)
  Bottom Layer w15: U3.1 1400.28,697.56 C19.2 1440,747.56 R17.2 1442.44,772.44 v1(1475,805)
NetC20_2: C20.2 R17.1 | length 53.5
  Bottom Layer w15: C20.2 1495,747.44 R17.1
NetC21_1: C21.1 D7.2 R19.2
NetC22_1: C22.1 R20.1 U1.10 | length 806.3
  MidLayer2 w15: v1(70,105) 207.17,242.17 v1(207.17,605)
  Bottom Layer w10: v1(207.17,605) 207.87,604.29 U1.10
  Bottom Layer w15: v1(70,105) 65,105 82.44,122.44 C22.1 82.44,305 R20.1
NetD1_2: D1.2 Q1.5 Q1.6 Q1.7 Q1.8 Q1.9 T1.4 T1.5
  other v1: 730,510 630,565 630,615 680,615 630,665
NetD2_2: D2.2 D7.1 R2.1 T1.6
  other v1: 1175,535 1280,565
NetQ1_1: Q1.1 Q1.2 Q1.3 R6.1 R8.2 | length 183.2
  Bottom Layer w15: R6.1 470,300 470,405.53 Q1.3
NetQ1_4: Q1.4 R4.2 | length 66.3
  Bottom Layer w15: R4.2@352.56,405 Q1.4@418.81,405
NetR3_1: R3.1 R5.2 U1.2 | length 288.8
  Top Layer w15: R5.2 R3.1 192.44,762.56 207.17,747.83 207.17,712.83 v1(235,685)
  Bottom Layer w10: v1(235,685) 260.31,710.31 U1.2
NetR4_1: R4.1 U1.8 | length 206.5
  Bottom Layer w10: 280,525 U1.8
  Bottom Layer w15: 280,525 297.44,507.56 R4.1@297.44,405
NetR13_2: R13.2 U1.6 | length 76.2
  Top Layer w15: v1(352.83,605) R13.2
  Bottom Layer w10: U1.6 352.13,604.29 v1(352.83,605)
NetR14_1: R14.1 U2.1 | length 61.1
  Top Layer w15: R14.1 957.44,712.44 U2.1
NetT1_7: T1.7 T1.8 | length 98.4
  Top Layer w40: T1.8 T1.7
PWRGND: C1.2 C5.2 C6.2 C7.2 C13.2 C15.2 C16.2 C17.2 C22.2 J1.2 R5.1 R8.1 R13.1 U1.4 U1.5 U1.7 U2.3 | length 594.2
  Top Layer w15: v1(90,655) R5.1 ; C17.2@309.53,765.71 328.82,785 370,785 v1(375,780) 365,770 365,714.72 R13.1 ; U2.3 v1(710,825)
  Bottom Layer w10: U1.7 299.68,644.68 330,675 330,705 319.37,715.63 U1.5 ; U1.4 U1.5 ; v1(375,780) 359.29,780 345,765.71 U1.5
  Bottom Layer w15: C16.2 C15.2
  other v1: 230,70 285,70 230,130 285,130 230,185 285,185 750,280 750,335
pads on no net: T1.2 T1.9

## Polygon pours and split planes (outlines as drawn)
PWRGND on MidLayer2 "MidLayer2-PWRGND" (solid, remove dead copper, pour order 62): 840,515 840,517.65 770,587.65 770,875 25.26,875 25.26,25.26 840,25.26
GND on MidLayer2 "MidLayer2-GND" (solid, remove dead copper, pour order 64): 865,875 865,615 865,614.1 930,549.1 930,25.26 1775,25.26 1775,875
GND on MidLayer1 "MidLayer1-GND" (solid, remove dead copper, pour order 60): 865,875 865,615 930,550 930,25.26 1775,25.26 1775,875
PWRGND on MidLayer1 "MidLayer1-PWRGND" (solid, remove dead copper, pour order 61): 770,875 770,585 840,515 840,25.26 25.26,25.26 25.26,875
NetD2_2 on Bottom Layer "NETD2_2_L04_P055" (solid, remove dead copper, pour order 55): 1490,430 1210,430 1210,460 1150,520 1150,585 1290,585 1385,490 1490,490
NetD1_2 on Bottom Layer "Bottom Layer-D1_2" (solid, remove dead copper, pour order 45): 405,445 405,700 635,700 635,698.35 755,578.35 755,445
NetQ1_1 on Bottom Layer "Bottom Layer-Q1_1" (solid, remove dead copper, pour order 46): 455,420 455,120 585,120 585,420
NetC21_1 on Bottom Layer "Bottom Layer-C21_1" (solid, remove dead copper, pour order 54): 1110,352.5 1110,95 1305,95 1305,352.5
GND on Bottom Layer "Bottom Layer-GND" (solid, remove dead copper, pour order 56): 930,25 930,550 865,615 865,875 1775,875 1775,25
PWRGND on Bottom Layer "Bottom Layer-PWRGND" (solid, remove dead copper, pour order 57): 840,25 840,515 770,585 770,875 25,875 25,25
NetC7_1 on Top Layer "Top Layer-C7_1" (solid, remove dead copper, pour order 43): 26.14,235 25,236.14 25,505 150,505 150,550 205,550 285,550 285,235
NetD1_2 on Top Layer "Top Layer-D1_2" (solid, remove dead copper, pour order 44): 755,385 600,385 600,600 565,635 405,635 405,750 585,750 755,578.35
NetC2_2 on Top Layer "Top Layer-C2_2" (solid, remove dead copper, pour order 47): 700,350 580,350 580,385 385,385 385,550 310,550 310,310 410,310 410,25 700,25
NetC4_2 on Top Layer "Top Layer-C4_2" (solid, remove dead copper, pour order 48): 425,395 425,585 570,585 570,395
NetC3_1 on Top Layer "Top Layer-C3_1" (solid, remove dead copper, pour order 49): 1775,400 1350,400 1350,190 1775,190
NetC11_1 on Top Layer "Top Layer-C11_1" (solid, remove dead copper, pour order 50): 1355,875 1355,620 1495,620 1540,575 1540,435 1775,435 1775,685 1570,685 1495,760 1495,875
NetD2_2 on Top Layer "Top Layer-D2_2" (solid, remove dead copper, pour order 51): 1150,475 1350,475 1350,440 1500,440 1500,585.31 1150,584.88
GND on Top Layer "Top Layer-GND" (solid, remove dead copper, pour order 58): 930,25.26 930,550 865,615 865,875 1775,875 1775,25.26
PWRGND on Top Layer "Top Layer-PWRGND" (solid, remove dead copper, pour order 59): 25.26,25.26 839.74,25.26 840,25 840,515 770,585 770,875 25.26,875

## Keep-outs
Keep-Out Layer:
  lines w10: 1810,915 0,915 ; 1815,910 1815,0 ; -5,0 ccw(c0,0) 0,-5 ; -5,0 ccw(c0,0) 0,-5 ; -5,0 -5,910 ; -5,910 cw(c0,910) 0,915 ; -5,910 cw(c0,910) 0,915 ; 0,-5 1810,-5 ; 1810,-5 ccw(c1810,0) 1815,0 ; 1810,-5 ccw(c1810,0) 1815,0
  text ".Layer_Name" at 577,-858.49 h60

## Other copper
Top Layer:
  text ".Layer_Name" at 577,-858.49 h60
Bottom Layer:
  text ".Layer_Name" at 577,-858.49 h60

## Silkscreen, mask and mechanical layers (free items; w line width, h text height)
Top Overlay:
  text "-" at 1285,730.12 h40
  text "+" at 1380,730.12 h40
  text "-" at 155,525 h40
  text "+" at 155,420 h40
  text ".Layer_Name" at 577,-858.49 h60
Bottom Overlay:
  lines w10: 180,762.56 200,782.56 200,800
  text ".PCB_Rev" at 360,49.88 h40
  text ".PRJ_Number" at 695.43,50.43 h40
  text ".Layer_Name" at 577,-858.49 h60
Top Paste:
  text ".Layer_Name" at 577,-858.49 h60
Bottom Paste:
  text ".Layer_Name" at 577,-858.49 h60
Top Solder:
  text ".Layer_Name" at 577,-858.49 h60
  text ".Layer_Name" at 577,-858.49 h60
Bottom Solder:
  text ".Layer_Name" at 577,-858.49 h60
Drill Guide:
  text ".Layer_Name" at 577,-858.49 h60
M1 Board Outline:
  the board outline again, w10
  text ".Layer_Name" at 577,-858.49 h60
M2 Board Dimensions:
  rectangle: 0,-285.5 125,-160.5
  rectangle: 125,-410.5 500,-285.5
  lines w7: 0,-285.5 1000,-285.5 ; 125,-410.5 125,-160.5 ; 250,-410.5 250,-160.5 ; 500,-410.5 500,-160.5 ; 750,-410.5 750,-160.5 ; 0,-410.5 1000,-410.5 1000,-160.5 0,-160.5 0,-410.5
  text ".Layer_Name" at 577,-858.49 h60
M3 3D STEP Top:
  text ".Layer_Name" at 577,-858.49 h60
M4 3D STEP Bottom:
  text ".Layer_Name" at 577,-858.49 h60
M5 Assembly Top:
  lines w10: -292,-930.17 6308,-930.17 ; -292,-726.83 6310,-726.83 ; -292,-523.5 -292,-1133.5 3713,-1133.5 6310,-1133.5 6310,-523.5 -291.5,-523.5 -291.5,-1133.5 1284,-1133.5 ; 2173,-1133.5 2173,-523.5 ; 3440,-726.83 3440,-523.5 ; 4280,-726.83 4280,-523.5 ; 4902,-1140 4902,-937.17
  text "COMPONENTS MARKED 'DNP' SHOULD NOT BE POPULATED." at 1153.5,-318.5 h60
  text "ASSEMBLY VARIANT:" at 1153,-434 h60
  text ".VariantName" at 2189,-434 h60
  text "PCB VIEWED FROM TOP SIDE" at -228.5,-655.67 h60
  text "BOARD #:" at 2248,-655.67 h60
  text ".PRJ_Number" at 2793.5,-655.67 h60
  text "REV:" at 3638,-655.67 h60
  text ".PCB_Rev" at 3929.5,-655.67 h60
  text "SVN REV:" at 4476,-655.67 h60
  text ".VersionControl_RevNumber" at 4982,-655.67 h60
  text "IGNORE ->" at -228.5,-858.49 h60
  text "PLOT NAME =" at -228.5,-1064.34 h60
  text ".plot_File_Name" at 577,-1064.34 h60
  text "GENERATED    :" at 2250,-1064.34 h60
  text ".Print_Date" at 3119.5,-1064.34 h60
  text ".Print_Time" at 3848.5,-1064.34 h60
  text "TEXAS INSTRUMENTS" at 5113,-1064.34 h60
M6 Assembly Bottom:
  lines w10: -292.5,-727.33 6309.5,-727.33 ; -290.5,-930.67 6309.5,-930.67 ; 1115.5,-1140.5 1115.5,-937.67 ; 1737.5,-727.33 1737.5,-524 ; 2577.5,-727.33 2577.5,-524 ; 3844.5,-1134 3844.5,-524 ; 4733.5,-1134 6309,-1134 6309,-524 -292.5,-524 -292.5,-1134 2304.5,-1134 6309.5,-1134 6309.5,-524
  text "COMPONENTS MARKED 'DNP' SHOULD NOT BE POPULATED." at 6102,-318 h60
  text ".VariantName" at 5058,-434 h60
  text "ASSEMBLY VARIANT:" at 6097,-434 h60
  text ".VersionControl_RevNumber" at 1035.5,-656.17 h60
  text "SVN REV:" at 1541.5,-656.17 h60
  text ".PCB_Rev" at 2088,-656.17 h60
  text "REV:" at 2379.5,-656.17 h60
  text ".PRJ_Number" at 3224,-656.17 h60
  text "BOARD #:" at 3769.5,-656.17 h60
  text "PCB VIEWED FROM BOTTOM SIDE" at 6246,-656.17 h60
  text "IGNORE ->" at 2547.85,-858.49 h60
  text "TEXAS INSTRUMENTS" at 904.5,-1064.84 h60
  text ".Print_Time" at 2169,-1064.84 h60
  text ".Print_Date" at 2898,-1064.84 h60
  text "GENERATED    :" at 3767.5,-1064.84 h60
  text ".plot_File_Name" at 5440.5,-1064.84 h60
  text "PLOT NAME =" at 6246,-1064.84 h60
M9 Title Sheet:
  drawing of 57 lines, arcs and shapes, not listed
  text "1" at 739.84,8036.5 h70
  text "2" at 3235.5,8036.5 h70
  text "3" at 5724.84,8036.5 h70
  text "4" at 8231.51,8036.5 h70
  text "5" at 10730.5,8036.5 h70
  text "6" at 13235.5,8036.5 h70
  text "A" at -416.5,6893.5 h70
  text "A" at 14383.5,6893.5 h70
  text "B" at -416.5,4513.5 h70
  text "B" at 14383.5,4513.5 h70
  text "C" at -416.5,2138.5 h70
  text "C" at 14383.5,2138.5 h70
  text "PROJECT TITLE:" at 11343.5,277.5 h45
  text ".PRJ_Title" at 11393.5,144.17 h70
  text "DESIGNED FOR:" at 11343.5,-23.5 h45
  text ".PRJ_Customer" at 11393.5,-163.5 h70
  text "D" at -416.5,-231.5 h70
  text "D" at 14383.5,-231.5 h70
  text "FILE NAME:" at 11343.5,-323.5 h45
  text ".PCB_File_Name_No_Path" at 11393.5,-443.5 h70
  text "Texas Instruments (TI) and/or its licensors do not warrant the accuracy or completeness of this specification" at 6374,-605.34 h45
  text "ENGINEER:" at 11343.5,-613.5 h45
  text "LAYOUT BY:" at 12848.5,-613.5 h45
  text "or any information contained therein. TI and/or its licensors do not warrant that this design will meet" at 6329.01,-718 h45
  text ".PRJ_Engineer" at 11393.5,-768.49 h70
  text ".PCB_Layout" at 12899,-768.49 h70
  text "the specifications, will be suitable for your application or fit for any particular purpose, or will operate in" at 6329.01,-830.67 h45
  text ".Layer_Name" at 577,-858.49 h60
  text "ALTIUM DESIGNER VERSION:" at 12848.5,-923.5 h45
  text "an implementation. TI and/or its licensors do not warrant that the design is production worthy. You should" at 6329.01,-943.33 h45
  text "completely validate and test your design implementation to confirm the system functionality for your application." at 6374,-1056 h45
  text ".print_Scale" at 11393.5,-1056.83 h70
  text ".Application_BuildNumber" at 12899,-1056.83 h70
  text "1" at 739.84,-1263.5 h70
  text "2" at 3235.5,-1263.5 h70
  text "3" at 5724.84,-1263.5 h70
  text "4" at 8231.51,-1263.5 h70
  text "5" at 10730.5,-1263.5 h70
  text "6" at 13235.5,-1263.5 h70
M10 Fab Notes:
  drawing of 185 lines, arcs and shapes, not listed
  text "DESIGN INFORMATION" at 12381.02,5910 h60
  text "MIN. TRACK WIDTH:" at 11736.46,5730 h60
  text "8" at 12832.7,5730 h60
  text "MIL" at 12987.46,5730 h60
  text "MIN. CLEARANCE:" at 11736.46,5598 h60
  text "0.2" at 12772.7,5598 h60
  text "mm" at 12987.46,5598 h60
  text "MIN. VIA PAD SIZE:" at 11736.46,5466 h60
  text "24" at 12802.71,5466 h60
  text "MIL" at 12987.46,5466 h60
  text "0.05mm (2MIL)" at 12431.46,5324.29 h60
  text "MINIMUM ANNULAR RING" at 11407.23,5320 h60
  text "EXTERNAL" at 13139.46,5320 h60
  text "PER" at 11607.23,5202 h60
  text "IPC-D-275 CLASS 2 LEVEL C" at 11827.23,5202 h60
  text "MIL, HOLES" at 13315.46,5089.71 h60
  text "+/-" at 12923,5089 h60
  text "+/-" at 13777,5089 h60
  text "REGISTRATION TOLERANCES:" at 11407.23,5084 h60
  text "METAL" at 12607,5084 h60
  text "5" at 13183.2,5084 h60
  text "3" at 14016.2,5084 h60
  text "MIL" at 14132.46,5084 h60
  text "MATERIAL:" at 11332.46,4874.54 h60
  text "FR-4 High Tg" at 12318.9,4734.21 h60
  text "FR-408" at 11753.46,4725.64 h60
  text "X" at 12165.46,4725.64 h60
  text "OTHER" at 13241.46,4725.64 h60
  text "62 MIL (1.6mm) +/-10%" at 12073.56,4562.92 h60
  text "THICKNESS:" at 11407.23,4558.64 h60
  text "X" at 11945.4,4558.64 h60
  text "OTHER" at 13358.46,4558.64 h60
  text "TOLERANCE:" at 11407.23,4400.64 h60
  text "X" at 12246.53,4400.64 h60
  text "ANSI IPC-6012 TYPE 3 CLASS 2" at 12433.48,4400.64 h60
  text "OTHER +/-" at 12433.46,4244.64 h60
  text "BOW & TWIST:" at 11407.23,4087.64 h60
  text "X" at 12246.53,4087.64 h60
  text "ANSI IPC-6012 TYPE 3 CLASS 2" at 12433.48,4087.64 h60
  text "OTHER +/-" at 12433.46,3929.13 h60
  text "DRILLING:" at 11332.46,3790.64 h60
  text "REFERENCE:" at 11407.23,3673.64 h60
  text "X" at 12055.46,3673.64 h60
  text "AS SHOWN" at 12242.46,3673.64 h60
  text "X" at 12956.46,3673.64 h60
  text "NC_DRILL FILES" at 13093.46,3673.64 h60
  text "PTH MIN COPPER THICKNESS:" at 11407.23,3515.64 h60
  text "X" at 12757.46,3515.64 h60
  text "1MIL" at 12894.46,3515.64 h60
  text "OTHER" at 13391.46,3515.64 h60
  text "BOARD FINISH:" at 11332.46,3356.64 h60
  text "SILKSCREEN:" at 11487.68,3238.64 h60
  text "X" at 12436.46,3238.64 h60
  text "TOP" at 12562.46,3238.64 h60
  text "X" at 12946.46,3238.64 h60
  text "BOTTOM" at 13073.46,3238.64 h60
  text "SILKSCREEN COLOR:" at 11487.68,3071.64 h60
  text "X" at 12435.42,3071.64 h60
  text "WHITE" at 12562.46,3071.64 h60
  text "OTHER" at 13073.46,3071.64 h60
  text "SOLDER RESIST COLOR:" at 11487.68,2901.64 h60
  text "X" at 12055.42,2742.44 h60
  text "GREEN" at 12182.46,2742.44 h60
  text "BLUE" at 12773.46,2742.44 h60
  text "OTHER" at 13311.46,2742.44 h60
  text "X" at 12215,2560 h60
  text "IMMERSION GOLD (ENIG)" at 12393.46,2553.92 h60
  text "ENEPIG" at 13731,2550.64 h60
  text "SURFACE FINISH:" at 11332.46,2549.64 h60
  text "IMM. TIN/SILVER OR EQUIV" at 11662,2392.64 h60
  text "OTHER" at 13093.46,2392.64 h60
  text "X" at 12205,2215 h60
  text "ARRAY/PANEL:" at 11332.46,2213.64 h60
  text "CUT AND TRIM PER MECH LAYER 1" at 12393.46,2209.35 h60
  text "N.C. ROUTE" at 12393.46,2057.64 h60
  text "V. SCORE" at 13259.46,2057.64 h60
  text "CERTIFICATION:" at 11332.46,1920.64 h60
  text "MATERIALS AND WORKMANSHIP FOR ALL PCBS" at 12057.46,1920.64 h60
  text "TO MEET OR EXCEED THE REQUIREMENTS OF:" at 12057.46,1822.64 h60
  text "X" at 11683.96,1686.13 h60
  text "ANSI IPC-A-600F CLASS ->" at 11822.96,1686.13 h60
  text "X" at 13462.02,1686.13 h60
  text "2" at 13580.96,1686.14 h60
  text "1" at 13265.96,1684.64 h60
  text "3" at 13934.96,1684.64 h60
  text "X" at 11686.02,1526.64 h60
  text "UL 94V-0" at 11822.96,1526.64 h60
  text "X" at 12498.02,1526.64 h60
  text "RoHS" at 12634.96,1526.64 h60
  text "OTHER" at 13279.36,1526.64 h60
  text "PER ORDER" at 13676.42,1526.64 h60
  text "ADDITIONAL REQUIREMENTS:" at 11332.46,1385.64 h60
  text "MICROSECTION:" at 11407.23,1270.64 h60
  text "YES" at 12312.96,1270.64 h60
  text "X" at 13050,1120 h60
  text "REQUIRED" at 13174.46,1114.49 h60
  text "BARE BOARD ELEC. TEST:" at 11407.23,1111.64 h60
  text "NONE" at 12712.96,1111.64 h60
  text "PER ORDER" at 13766.46,1111.64 h60
  text "MANUFACTURER'S UL:" at 11407.23,954.64 h60
  text "RAIL" at 12572.96,950.35 h60
  text "METAL" at 13064.77,950.35 h60
  text "X" at 13440,950 h60
  text "SILK" at 13576.46,950.35 h60
  text ".Layer_Name" at 577,-858.49 h60
M11 Gerber Information:
  lines w10: -292,-930.17 6308,-930.17 ; -292,-726.83 6310,-726.83 ; -292,-523.5 -292,-1133.5 3713,-1133.5 6310,-1133.5 6310,-523.5 -291.5,-523.5 -291.5,-1133.5 1284,-1133.5 ; 2173,-1133.5 2173,-523.5 ; 3440,-726.83 3440,-523.5 ; 4280,-726.83 4280,-523.5 ; 4902,-1140 4902,-937.17
  text "ALL ARTWORK VIEWED FROM TOP SIDE" at -228.5,-655.67 h60
  text "BOARD #:" at 2248,-655.67 h60
  text ".PRJ_Number" at 2793.5,-655.67 h60
  text "REV:" at 3638,-655.67 h60
  text ".PCB_Rev" at 3929.5,-655.67 h60
  text "SVN REV:" at 4476,-655.67 h60
  text ".VersionControl_RevNumber" at 4982,-655.67 h60
  text "LAYER NAME =" at -228.5,-858.49 h60
  text "PLOT NAME =" at -228.5,-1064.34 h60
  text ".plot_File_Name" at 577,-1064.34 h60
  text "GENERATED    :" at 2250,-1064.34 h60
  text ".Print_Date" at 3119.5,-1064.34 h60
  text ".Print_Time" at 3848.5,-1064.34 h60
  text "TEXAS INSTRUMENTS" at 5113,-1064.34 h60
M12 Stackup:
  drawing of 295 lines, arcs and shapes, not listed
  text "Layer" at 9705.74,7665 h60
  text "Name" at 10115.65,7665 h60
  text "Material" at 11045.4,7665 h60
  text "Thickness" at 11905.16,7665 h60
  text "Constant" at 12555,7665 h60
  text "Board Layer Stack" at 13124.86,7665 h60
  text "1" at 9705.74,7545 h60
  text "Top Overlay" at 10115.65,7545 h60
  text "2" at 9705.74,7425 h60
  text "Top Solder" at 10115.65,7425 h60
  text "Solder Resist" at 11045.4,7425 h60
  text "0.40mil" at 11905.16,7425 h60
  text "3.5" at 12555,7425 h60
  text "3" at 9705.74,7305 h60
  text "Top Layer" at 10115.65,7305 h60
  text "Copper" at 11045.4,7305 h60
  text "2.80mil" at 11905.16,7305 h60
  text "4" at 9705.74,7185 h60
  text "Dielectric1" at 10115.65,7185 h60
  text "FR-4" at 11045.4,7185 h60
  text "20.00mil" at 11905.16,7185 h60
  text "4.8" at 12555,7185 h60
  text "5" at 9705.74,7065 h60
  text "MidLayer1" at 10115.65,7065 h60
  text "Copper" at 11045.4,7065 h60
  text "2.80mil" at 11905.16,7065 h60
  text "6" at 9705.74,6945 h60
  text "Dielectric2" at 10115.65,6945 h60
  text "FR-4" at 11045.4,6945 h60
  text "10.00mil" at 11905.16,6945 h60
  text "4.8" at 12555,6945 h60
  text "7" at 9705.74,6825 h60
  text "MidLayer2" at 10115.65,6825 h60
  text "Copper" at 11045.4,6825 h60
  text "2.80mil" at 11905.16,6825 h60
  text "8" at 9705.74,6705 h60
  text "Dielectric3" at 10115.65,6705 h60
  text "FR-4" at 11045.4,6705 h60
  text "20.00mil" at 11905.16,6705 h60
  text "4.8" at 12555,6705 h60
  text "9" at 9705.74,6585 h60
  text "Bottom Layer" at 10115.65,6585 h60
  text "Copper" at 11045.4,6585 h60
  text "2.80mil" at 11905.16,6585 h60
  text "10" at 9705.74,6465 h60
  text "Bottom Solder" at 10115.65,6465 h60
  text "Solder Resist" at 11045.4,6465 h60
  text "0.40mil" at 11905.16,6465 h60
  text "3.5" at 12555,6465 h60
  text "11" at 9705.74,6345 h60
  text "Bottom Overlay" at 10115.65,6345 h60
  text ".Layer_Name" at 577,-858.49 h60
M13 Component Bodies Top:
  text ".Layer_Name" at 577,-858.49 h60
M14 Component Bodies Bottom:
  text ".Layer_Name" at 577,-858.49 h60
M15 Courtyards Top:
  text ".Layer_Name" at 577,-858.49 h60
M16 Courtyards Bottom:
  text ".Layer_Name" at 577,-858.49 h60
Drill Drawing:
  lines w10: 2256.09,164.34 2311.34,164.34 2311.34,219.59 2256.09,219.59 2256.09,164.34 ; 2256.09,343.91 2311.34,343.91 2283.72,288.66 2256.09,343.91
  lines w12: 2206,127.04 5437.49,127.04 ; 2206,375.68 5437.49,375.68 ; 2543.86,2.72 2543.86,500 ; 2875.86,2.72 2875.86,500 ; 3512.43,2.72 3512.43,500 ; 3771.57,2.72 3771.57,500 ; 4146.72,2.72 4146.72,500 ; 4871.05,2.72 4871.05,500 ; 2206,2.72 5437.49,2.72 5437.49,500 2206,500 2206,2.72
  text "Symbol" at 2280.59,412.98 h72
  text "Quantity" at 2581.16,412.98 h72
  text "Finished Hole Size" at 2913.16,412.98 h72
  text "Plated" at 3549.72,412.98 h72
  text "Hole Type" at 3808.86,412.98 h72
  text "Drill Layer Pair" at 4184.02,412.98 h72
  text "Hole Tolerance" at 4908.35,412.98 h72
  text "42" at 2581.16,288.66 h60
  text "16.00mil (0.406mm)" at 2913.16,288.66 h60
  text "PTH" at 3549.72,288.66 h60
  text "Round" at 3808.86,288.66 h60
  text "Top Layer - Bottom Layer" at 4184.02,288.66 h60
  text "4" at 2581.16,164.34 h60
  text "40.00mil (1.016mm)" at 2913.16,164.34 h60
  text "PTH" at 3549.72,164.34 h60
  text "Round" at 3808.86,164.34 h60
  text "Top Layer - Bottom Layer" at 4184.02,164.34 h60
  text "46 Total" at 2581.16,40.02 h60
  text ".Layer_Name" at 577,-858.49 h60

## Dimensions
0,0 to 0,910 on M2 Board Dimensions
0,0 to 1810,0 on M2 Board Dimensions
0,-410.5 to 1000,-410.5 on M2 Board Dimensions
